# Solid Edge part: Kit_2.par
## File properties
Author: bmolnar
Last saved by: bmolnar
Revision: 78
Sűrűség: 0,000 kg/m^3
Pontosság: 0,990
Username: bmolnar
Dokumentum tartalom típus: 0
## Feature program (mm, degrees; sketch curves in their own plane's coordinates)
base feature "unnamed BaseFeature 1"
sketch for "unnamed Hole 1" plane through (36, 36, -84) normal (0, 0, -1) x-axis (0, -1, 0)
  hole centre (0, 0) bore radius 4.188
hole "unnamed Hole 1" through
sketch for "unnamed Hole 2" plane through (36, 36, -84) normal (0, 0, -1) x-axis (0, -1, 0)
  hole centre (0, 72) bore radius 4.188
hole "unnamed Hole 2" through
sketch for "unnamed Hole 3" plane through (36, 36, -84) normal (0, 0, -1) x-axis (0, -1, 0)
  hole centre (72, 72) bore radius 4.188
hole "unnamed Hole 3" through
sketch for "unnamed Hole 4" plane through (36, 36, -84) normal (0, 0, -1) x-axis (0, -1, 0)
  hole centre (72, 0) bore radius 4.188
hole "unnamed Hole 4" through
pattern "unnamed Pattern 1" of "unnamed Hole 1", "unnamed Hole 2", "unnamed Hole 3", "unnamed Hole 4"
sketch for "Furat_6" plane through (-47.6845, 0, -79.5) normal (-0.999962, 0, -0.008727) x-axis (0, -1, 0)
  hole centre (-0.0008, 0.4997) bore radius 4.283
hole "Furat_6" nominal diameter 9.728 finite  ThreadDepth = 10 mm
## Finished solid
Body 1: solid body, 307 faces, 739 edges, 449 vertices.
  Faces by surface: plane 139, cylinder 73, swept 60, cone 24, torus 10, spline 1
  Edges by curve: line 421, circle 152, spline 120, ellipse 32, curve on surface 14
Bounding box of the edges (mm; curved faces can reach further): 95.500 x 95.500 x 15.000, from (-47.75, -47.75, -87) to (47.75, 47.75, -72).
Cylindrical faces by radius (mm): R0.2 x48, R0.2017 x2, R0.2018 x2, R4.188 x4, R4.283 x1, R4.9 x4, R5.15 x4, R6.75 x4, R10.3 x1, R10.95 x1, R11.5 x1, R12.5 x1
Conical faces (half-angle, radius in mm at the cone's reference point): 0.5 deg R10 x4, 0.5 deg R13.5 x2, 7 deg R11.7695 x1, 14 deg R10.15 x1, 14 deg R10.557 x1, 17 deg R10.15 x1, 23 deg R10.9211 x1, 42.5 deg R10.137 x1, 45 deg R4.185 x4, 45 deg R4.985 x4, 45 deg R11.1 x1, 84 deg R10.512 x1, 85 deg R12.1625 x1, 87 deg R10.2157 x1
Toroidal faces (ring radius, tube radius in mm): R4.7 r0.2 x8, R10.9008 r0.225 x1, R11.3914 r0.325 x1
Planar faces by outward normal: +x 14, +y 14, +z 1, -x 16, -y 13, -z 19, oblique 62
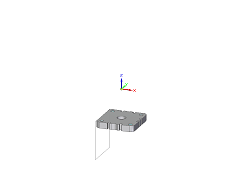
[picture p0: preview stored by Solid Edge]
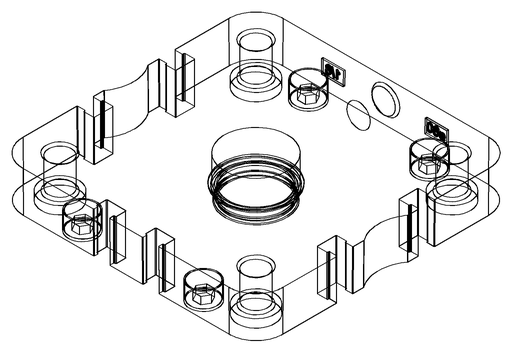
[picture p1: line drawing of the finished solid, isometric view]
